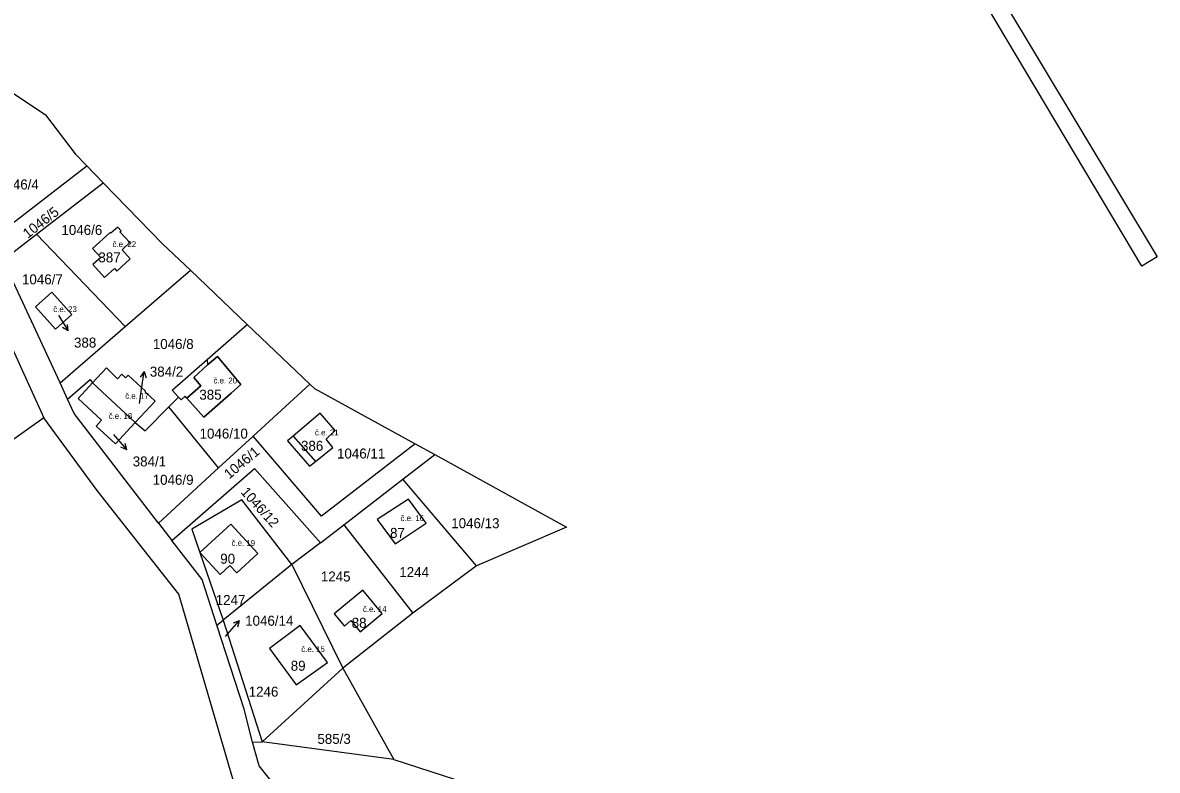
# Model space of a CAD drawing. Extents: x -887272 to -877616, y -1026687 to -1019819.
# Drawn here: x -884877.9 to -884684.7, y -1024619.5 to -1024492.3 of the extents above; entities that cross this region are included whole.
import ezdxf

# ---------------------------------------------------------------- set-up
doc = ezdxf.new("R2010")
doc.units = 0
for name, color, linetype in [('Definiční body', 7, 'Continuous'), ('Hranice parcel', 7, 'Continuous'), ('Parcelní čísla', 7, 'Continuous'), ('Polygon budovy', 7, 'Continuous'), ('Pop  PČ popisy', 7, 'Continuous'), ('Vnitřní kresba', 7, 'Continuous')]:
    doc.layers.add(name, color=color, linetype=linetype)

msp = doc.modelspace()

# ---------------------------------------------------------------- linework, layer by layer
at = {"layer": 'Hranice parcel'}
for p, q in [((-884882.65, -1024528.74), (-884866.95, -1024516.67)), ((-884866.95, -1024516.67), (-884864.17, -1024519.52)), ((-884875.53, -1024528.29), (-884864.17, -1024519.52)), ((-884881.09, -1024532.61), (-884875.53, -1024528.29)), ((-884875.53, -1024528.29), (-884860.46, -1024543.98)), ((-884860.46, -1024543.98), (-884849.32, -1024534.42)), ((-884849.32, -1024534.42), (-884839.65, -1024543.63)), ((-884883.3, -1024539.78), (-884874.31, -1024559.51)), ((-884846.49, -1024549.62), (-884839.65, -1024543.63)), ((-884839.65, -1024543.63), (-884828.98, -1024553.78)), ((-884871.52, -1024553.6), (-884860.46, -1024543.98)), ((-884870.24, -1024556.36), (-884871.52, -1024553.6)), ((-884858.72, -1024560.33), (-884865.99, -1024553.59)), ((-884828.98, -1024553.78), (-884838.64, -1024562.64)), ((-884853.02, -1024557.69), (-884851.35, -1024556)), ((-884844.56, -1024568.06), (-884853.02, -1024557.69)), ((-884874.31, -1024559.51), (-884954.52, -1024616.8)), ((-884838.64, -1024562.64), (-884844.56, -1024568.06)), ((-884811.05, -1024563.97), (-884807.74, -1024565.8)), ((-884813.14, -1024570), (-884807.74, -1024565.8)), ((-884844.56, -1024568.06), (-884854.75, -1024577.44)), ((-884823.18, -1024577.72), (-884813.14, -1024570)), ((-884800.62, -1024584.74), (-884813.14, -1024570)), ((-884854.75, -1024577.44), (-884852.47, -1024580.4)), ((-884827.19, -1024580.8), (-884823.18, -1024577.72)), ((-884823.18, -1024577.72), (-884811.44, -1024592.78)), ((-884827.19, -1024580.8), (-884832.04, -1024584.52)), ((-884832.04, -1024584.52), (-884843.76, -1024593.98)), ((-884832.04, -1024584.52), (-884823.36, -1024602.12)), ((-884800.62, -1024584.74), (-884811.44, -1024592.78)), ((-884844.81, -1024594.83), (-884843.76, -1024593.98)), ((-884843.76, -1024593.98), (-884837.14, -1024614.7)), ((-884811.44, -1024592.78), (-884823.36, -1024602.12)), ((-884837.14, -1024614.7), (-884823.36, -1024602.12)), ((-884823.36, -1024602.12), (-884814.72, -1024617.68)), ((-884838.76, -1024614.74), (-884837.14, -1024614.7)), ((-884814.72, -1024617.68), (-884837.14, -1024614.7)), ((-884814.72, -1024617.68), (-884800.18, -1024622.42))]:
    msp.add_line(p, q, dxfattribs=at)
for points in [[(-884867, -1024267.34), (-884875.02, -1024271.26), (-884886.68, -1024276.28), (-884897.76, -1024288.38), (-884904.78, -1024302.7), (-884909.14, -1024329.5), (-884908.7, -1024362.16), (-884905.12, -1024372.96), (-884897.2, -1024383.94), (-884887.36, -1024390.42), (-884869.88, -1024402.44), (-884820.08, -1024426.42), (-884760.96, -1024452.82), (-884728.26, -1024470.78), (-884711.24, -1024488.02), (-884684.7, -1024532.14), (-884687.32, -1024533.72), (-884713.62, -1024489.62), (-884730.14, -1024473.14), (-884761.82, -1024455.36), (-884820.76, -1024428.66), (-884872.5, -1024404.46), (-884889.62, -1024392.74)], [(-884891.84, -1024496.1), (-884873.98, -1024507.96), (-884868.98, -1024514.58), (-884866.95, -1024516.67)], [(-884864.17, -1024519.52), (-884854.08, -1024529.9), (-884849.32, -1024534.42)], [(-884860.61, -1024530.62), (-884859.66, -1024529.7), (-884861.32, -1024527.88), (-884861.13, -1024527.7), (-884861.71, -1024527.06), (-884862.89, -1024528.13), (-884863.02, -1024527.98), (-884866.02, -1024530.71), (-884864.6, -1024532.26), (-884865.92, -1024533.44), (-884863.93, -1024535.63), (-884862.26, -1024534.12), (-884861.86, -1024534.56), (-884859.57, -1024532.48), (-884860.97, -1024530.94), (-884860.61, -1024530.62)], [(-884871.52, -1024553.6), (-884880.12, -1024535.02), (-884881.09, -1024532.61)], [(-884875.72, -1024540.64), (-884872.3, -1024544.45), (-884869.52, -1024541.96), (-884872.94, -1024538.14), (-884875.72, -1024540.64)], [(-884846.49, -1024549.62), (-884846.43, -1024550.5), (-884844.74, -1024549.09), (-884840.73, -1024553.88), (-884842.38, -1024555.34), (-884847.05, -1024559.45), (-884849.93, -1024556.18)], [(-884858.72, -1024560.33), (-884855.35, -1024556.69), (-884857.06, -1024555.1), (-884856.97, -1024555), (-884859.93, -1024552.25), (-884860.37, -1024552.73), (-884861.03, -1024552.12), (-884861.73, -1024552.88), (-884863.61, -1024551.03), (-884865.99, -1024553.59)], [(-884851.35, -1024556), (-884852.42, -1024554.84), (-884846.49, -1024549.62)], [(-884870.24, -1024556.36), (-884866.39, -1024553.02), (-884865.99, -1024553.59)], [(-884865.99, -1024553.59), (-884868.44, -1024556.23), (-884864.46, -1024559.93), (-884865.39, -1024560.94), (-884862.11, -1024563.98), (-884858.72, -1024560.33)], [(-884828.98, -1024553.78), (-884828.18, -1024554.54), (-884811.05, -1024563.97)], [(-884854.75, -1024577.44), (-884869.1, -1024558.82), (-884870.24, -1024556.36)], [(-884849.93, -1024556.18), (-884850.21, -1024555.86), (-884850.9, -1024556.49), (-884851.35, -1024556)], [(-884858.72, -1024560.33), (-884857.02, -1024561.77), (-884853.02, -1024557.69)], [(-884832.8, -1024563.44), (-884829.08, -1024567.76), (-884828.04, -1024566.96), (-884825.08, -1024564.58), (-884826.23, -1024563.15), (-884824.68, -1024561.7), (-884827.24, -1024558.76), (-884831.85, -1024562.64), (-884832.8, -1024563.44)], [(-884872.76, -1024922.63), (-884842.58, -1024868.45), (-884811.61, -1024820.67), (-884781.27, -1024777.38), (-884766.7, -1024752.19), (-884758.6, -1024726.39), (-884763.88, -1024716.6), (-884777.17, -1024706.45), (-884796.59, -1024685.75), (-884810.2, -1024660.64), (-884842.12, -1024620.99), (-884851.29, -1024589.53), (-884865.18, -1024571.88), (-884874.31, -1024559.51)], [(-884811.05, -1024563.97), (-884827, -1024576.29), (-884838.64, -1024562.64)], [(-884807.74, -1024565.8), (-884785.3, -1024578.16), (-884800.62, -1024584.74)], [(-884852.47, -1024580.4), (-884838.4, -1024568.16), (-884827.19, -1024580.8)], [(-884832.04, -1024584.52), (-884840.6, -1024573.5), (-884849.06, -1024578.46)], [(-884814.46, -1024580.96), (-884809.18, -1024577.46), (-884812.2, -1024573.36), (-884817.52, -1024576.84), (-884814.46, -1024580.96)], [(-884849.06, -1024578.46), (-884847.7, -1024582.46), (-884843.76, -1024593.98)], [(-884837.83, -1024582.63), (-884842.43, -1024577.62), (-884847.7, -1024582.46), (-884844.26, -1024586.21), (-884842.6, -1024584.68), (-884841.44, -1024585.94), (-884837.83, -1024582.63)], [(-884844.81, -1024594.83), (-884847.34, -1024587.06), (-884852.47, -1024580.4)], [(-884821.99, -1024594.05), (-884820.42, -1024595.96), (-884816.68, -1024592.86), (-884819.98, -1024588.88), (-884824.88, -1024592.88), (-884823.12, -1024594.99), (-884821.99, -1024594.05)], [(-884838.76, -1024614.74), (-884840.18, -1024609.1), (-884844.81, -1024594.83)], [(-884826, -1024601.18), (-884830.64, -1024594.86), (-884835.88, -1024598.78), (-884831.34, -1024605), (-884826, -1024601.18)], [(-884818, -1024643.45), (-884820.18, -1024640.72), (-884837.62, -1024618.78), (-884838.76, -1024614.74)]]:
    msp.add_lwpolyline(points, dxfattribs=at)
at = {"layer": 'Polygon budovy'}
for points in [[(-884866.02, -1024530.71), (-884864.6, -1024532.26), (-884865.92, -1024533.44), (-884863.93, -1024535.63), (-884862.26, -1024534.12), (-884861.86, -1024534.56), (-884859.57, -1024532.48), (-884860.97, -1024530.94), (-884860.61, -1024530.62), (-884859.66, -1024529.7), (-884861.32, -1024527.88), (-884861.13, -1024527.7), (-884861.71, -1024527.06), (-884862.89, -1024528.13), (-884863.02, -1024527.98)], [(-884875.72, -1024540.64), (-884872.3, -1024544.45), (-884869.52, -1024541.96), (-884872.94, -1024538.14)], [(-884846.43, -1024550.5), (-884848.74, -1024552.69), (-884847.53, -1024554.07), (-884849.93, -1024556.18), (-884847.05, -1024559.45), (-884842.38, -1024555.34), (-884840.73, -1024553.88), (-884844.74, -1024549.09)], [(-884858.72, -1024560.33), (-884855.35, -1024556.69), (-884857.06, -1024555.1), (-884856.97, -1024555), (-884859.93, -1024552.25), (-884860.37, -1024552.73), (-884861.03, -1024552.12), (-884861.73, -1024552.88), (-884863.61, -1024551.03), (-884865.99, -1024553.59)], [(-884864.46, -1024559.93), (-884865.39, -1024560.94), (-884862.11, -1024563.98), (-884858.72, -1024560.33), (-884865.99, -1024553.59), (-884868.44, -1024556.23)], [(-884827.24, -1024558.76), (-884831.85, -1024562.64), (-884828.04, -1024566.96), (-884825.08, -1024564.58), (-884826.23, -1024563.15), (-884824.68, -1024561.7)], [(-884809.18, -1024577.46), (-884812.2, -1024573.36), (-884817.52, -1024576.84), (-884814.46, -1024580.96)], [(-884842.43, -1024577.62), (-884847.7, -1024582.46), (-884844.26, -1024586.21), (-884842.6, -1024584.68), (-884841.44, -1024585.94), (-884837.83, -1024582.63)], [(-884824.88, -1024592.88), (-884823.12, -1024594.99), (-884821.99, -1024594.05), (-884820.42, -1024595.96), (-884816.68, -1024592.86), (-884819.98, -1024588.88)], [(-884835.88, -1024598.78), (-884831.34, -1024605), (-884826, -1024601.18), (-884830.64, -1024594.86)]]:
    msp.add_lwpolyline(points, close=True, dxfattribs=at)
at = {"layer": 'Pop  PČ popisy'}
for p, q in [((-884871.79, -1024542.04), (-884871.71, -1024542.17)), ((-884871.71, -1024542.17), (-884870.16, -1024544.74)), ((-884870.16, -1024544.74), (-884870.25, -1024543.63)), ((-884870.16, -1024544.74), (-884871.11, -1024544.14)), ((-884857.23, -1024551.67), (-884857.87, -1024552.59)), ((-884857.65, -1024554.64), (-884857.23, -1024551.67)), ((-884857.23, -1024551.67), (-884856.88, -1024552.73)), ((-884857.99, -1024557.07), (-884857.65, -1024554.64)), ((-884862.41, -1024562.38), (-884862.13, -1024562.7)), ((-884862.13, -1024562.7), (-884860.16, -1024564.96)), ((-884860.16, -1024564.96), (-884861.2, -1024564.54)), ((-884860.16, -1024564.96), (-884860.44, -1024563.88)), ((-884842.99, -1024596.33), (-884841.02, -1024594.07)), ((-884841.02, -1024594.07), (-884842.06, -1024594.49)), ((-884841.02, -1024594.07), (-884841.3, -1024595.15)), ((-884843.37, -1024596.76), (-884842.99, -1024596.33))]:
    msp.add_line(p, q, dxfattribs=at)
at = {"layer": 'Vnitřní kresba'}
for p, q in [((-884848.74, -1024552.69), (-884846.43, -1024550.5)), ((-884847.53, -1024554.07), (-884848.74, -1024552.69)), ((-884849.93, -1024556.18), (-884847.53, -1024554.07)), ((-884831.85, -1024562.64), (-884828.04, -1024566.96))]:
    msp.add_line(p, q, dxfattribs=at)

# ---------------------------------------------------------------- texts
at = {"layer": 'Definiční body'}
for s, p in [('č.e. 22', (-884862.59, -1024530.48)), ('č.e. 23', (-884872.68, -1024541.54)), ('č.e. 20', (-884845.4, -1024553.69)), ('č.e. 17', (-884860.44, -1024556.3)), ('č.e. 18', (-884863.25, -1024559.73)), ('č.e. 21', (-884828.12, -1024562.53)), ('č.e. 16', (-884813.56, -1024577.11)), ('č.e. 19', (-884842.33, -1024581.33)), ('č.e. 14', (-884819.95, -1024592.59)), ('č.e. 15', (-884830.45, -1024599.4))]:
    msp.add_text(s, height=1, dxfattribs=at).set_placement(p)
at = {"layer": 'Parcelní čísla'}
for s, p in [('1046/4', (-884882.09, -1024520.67)), ('1046/6', (-884871.29, -1024528.41)), ('387', (-884865, -1024533.08)), ('1046/7', (-884878.01, -1024536.82)), ('388', (-884869.15, -1024547.58)), ('1046/8', (-884855.73, -1024547.82)), ('384/2', (-884856.24, -1024552.52)), ('385', (-884847.81, -1024556.45)), ('1046/10', (-884847.77, -1024563.07)), ('386', (-884830.5, -1024565.15)), ('1046/11', (-884824.37, -1024566.46)), ('384/1', (-884859.15, -1024567.81)), ('1046/9', (-884855.75, -1024570.93)), ('1046/13', (-884804.92, -1024578.32)), ('87', (-884815.34, -1024579.97)), ('90', (-884844.25, -1024584.37)), ('1245', (-884827.12, -1024587.39)), ('1244', (-884813.77, -1024586.65)), ('1247', (-884845.02, -1024591.39)), ('1046/14', (-884840.01, -1024594.92)), ('88', (-884821.87, -1024595.27)), ('89', (-884832.25, -1024602.58)), ('1246', (-884839.41, -1024606.99)), ('585/3', (-884827.71, -1024615.03))]:
    msp.add_text(s, height=1.7, dxfattribs=at).set_placement(p)
for s, rotation, p in [('1046/5', 38, (-884877.03, -1024529.09)), ('1046/1', 40, (-884842.72, -1024570.04)), ('1046/12', 312, (-884840.86, -1024572.25))]:
    msp.add_text(s, height=1.7, rotation=rotation, dxfattribs=at).set_placement(p)

doc.saveas('drawing.dxf')
